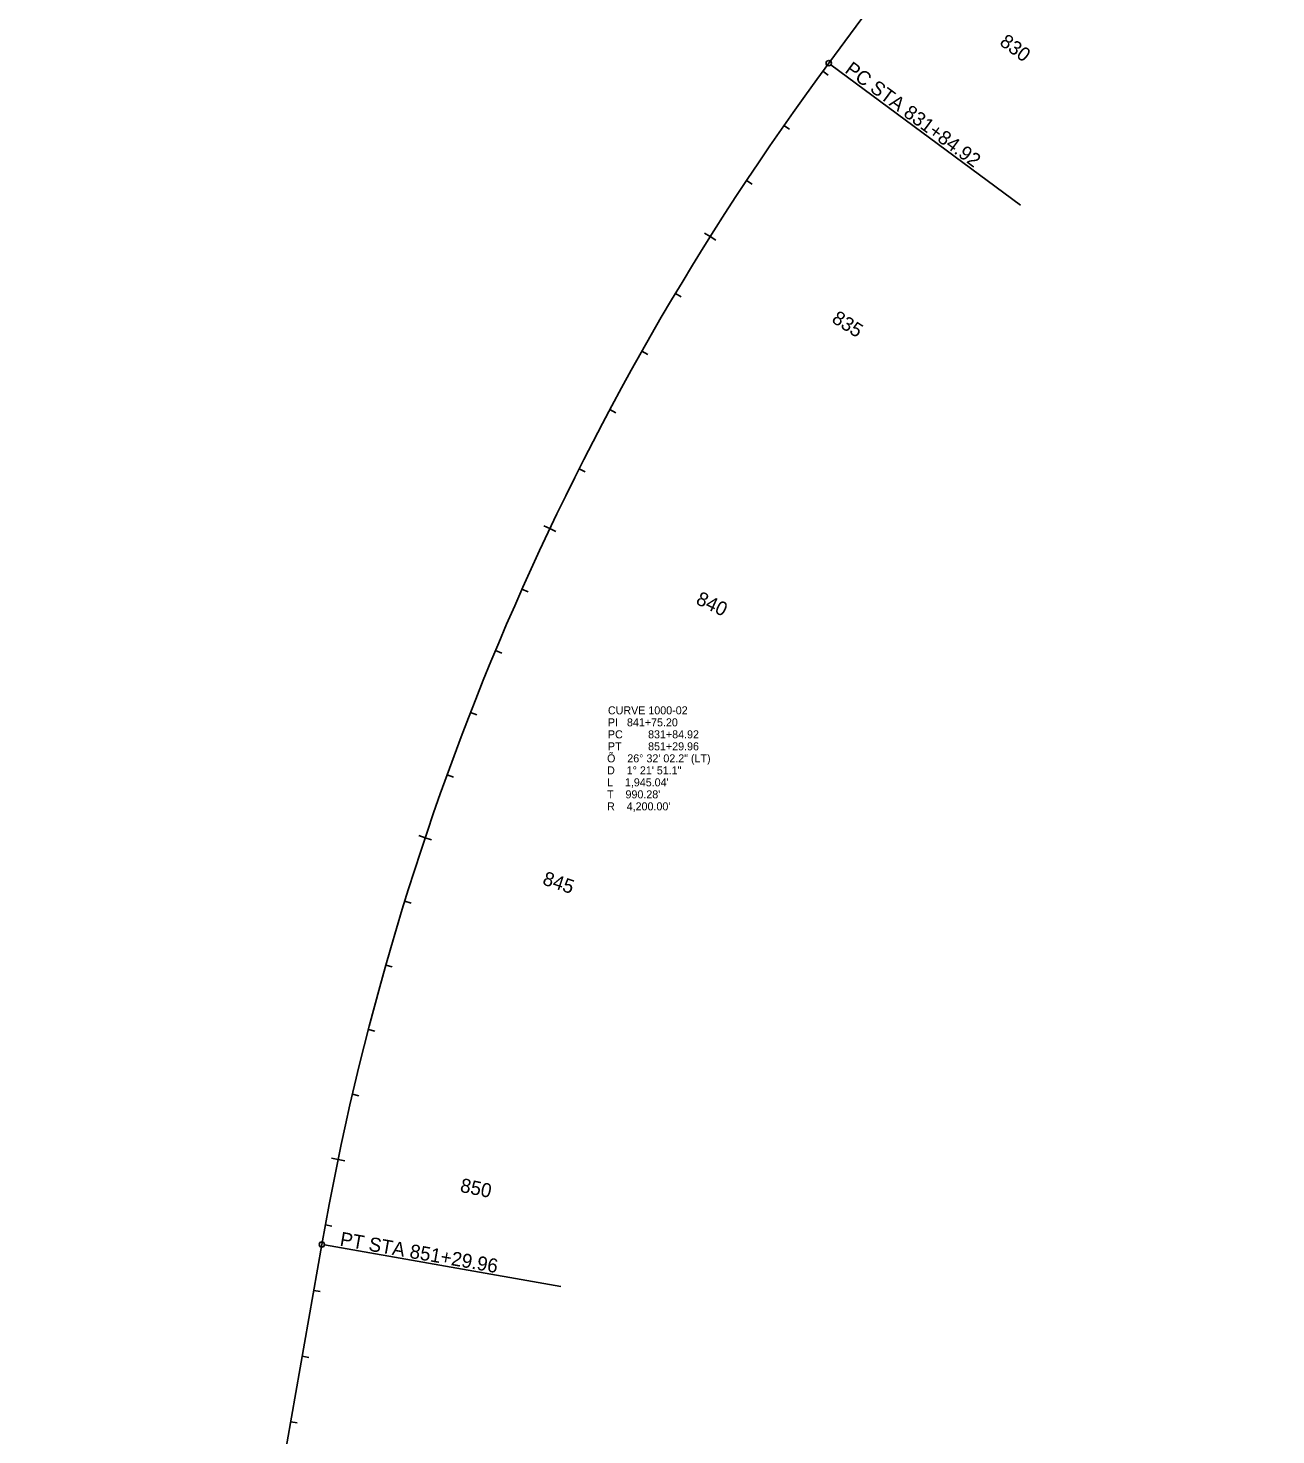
# Model space of a CAD drawing. Extents: x 2819977 to 2827606, y 113942 to 150283.
# Drawn here: x 2821007 to 2822878, y 134032 to 136141 of the extents above; entities that cross this region are included whole.
import ezdxf

# ---------------------------------------------------------------- set-up
doc = ezdxf.new("R2010")
doc.units = 0
for name, color, linetype in [('Level 63', 7, 'Continuous'), ('Roadway-Safety', 7, 'Continuous'), ('Roadway-Walls', 7, 'Continuous'), ('Utility-Power', 7, 'Continuous')]:
    doc.layers.add(name, color=color, linetype=linetype)

msp = doc.modelspace()

# ---------------------------------------------------------------- linework, layer by layer
at = {"layer": 'Level 63'}
for centre in [(2822207.8, 136088.7), (2821447.5, 134317.2)]:
    msp.add_circle(centre, 4, dxfattribs=at)
at = {"layer": 'Roadway-Safety'}
for p, q in [((2822211, 136086.3), (2822495.5, 135875.9)), ((2821451.5, 134316.6), (2821805.8, 134254.3))]:
    msp.add_line(p, q, dxfattribs=at)
at = {"layer": 'Utility-Power'}
for p, q in [((2822878.3, 136994.9), (2822207.8, 136088.7)), ((2822198.9, 136076.5), (2822206.9, 136070.6)), ((2822140.6, 135995.2), (2822148.8, 135989.5)), ((2822084.4, 135912.6), (2822092.7, 135907.1)), ((2822030.1, 135828.6), (2822021.6, 135833.9)), ((2822030.1, 135828.6), (2822038.5, 135823.3)), ((2821977.8, 135743.4), (2821986.4, 135738.2)), ((2821927.6, 135656.9), (2821936.3, 135652)), ((2821879.4, 135569.3), (2821888.3, 135564.5)), ((2821833.4, 135480.5), (2821842.3, 135476)), ((2821789.5, 135390.7), (2821780.4, 135394.9)), ((2821789.5, 135390.7), (2821798.5, 135386.4)), ((2821747.7, 135299.8), (2821756.8, 135295.7)), ((2821708.1, 135208), (2821717.3, 135204.1)), ((2821670.7, 135115.2), (2821680, 135111.6)), ((2821635.5, 135021.6), (2821644.9, 135018.2)), ((2821602.5, 134927.2), (2821593.1, 134930.4)), ((2821602.5, 134927.2), (2821612, 134924)), ((2821571.8, 134832.1), (2821581.4, 134829.1)), ((2821543.4, 134736.2), (2821553, 134733.5)), ((2821517.3, 134639.7), (2821527, 134637.2)), ((2821493.5, 134542.5), (2821503.2, 134540.3)), ((2821472, 134444.9), (2821462.2, 134446.9)), ((2821472, 134444.9), (2821481.8, 134442.8)), ((2821452.8, 134346.7), (2821462.6, 134344.9)), ((2821447.5, 134317.2), (2821007.1, 131809.7)), ((2821435.4, 134248.3), (2821445.2, 134246.5)), ((2821418.1, 134149.8), (2821427.9, 134148)), ((2821400.8, 134051.3), (2821410.6, 134049.6))]:
    msp.add_line(p, q, dxfattribs=at)
msp.add_arc((2825584.2, 133590.7), 4200, 143.5041, 170.0381, dxfattribs=at)

# ---------------------------------------------------------------- texts
at = {"layer": 'Roadway-Safety'}
for s, rotation, p in [('PC STA 831+84.92', 323.5041, (2822230.5, 136075.6)), ('PT STA 851+29.96', 350.0381, (2821473.6, 134315.7))]:
    msp.add_text(s, height=21, rotation=rotation, dxfattribs=at).set_placement(p)
at = {"layer": 'Roadway-Walls'}
for s, p in [('CURVE 1000-02', (2821876.6, 135112.2)), ('PI   841+75.20', (2821876.6, 135094.2)), ('PC', (2821876.6, 135076.2)), ('PT', (2821876.6, 135058.2)), ('831+84.92', (2821936.8, 135076.2)), ('851+29.96', (2821936.8, 135058.2)), ('Õ    26%%d 32\' 02.2" (LT)', (2821875.3, 135040.2)), ('D    1%%d 21\' 51.1"', (2821875.3, 135022.2)), ("L    1,945.04'", (2821875.3, 135004.2)), ("T    990.28'", (2821875.3, 134986.2)), ("R    4,200.00'", (2821875.3, 134968.2))]:
    msp.add_text(s, height=12, dxfattribs=at).set_placement(p)
at = {"layer": 'Utility-Power'}
for s, rotation, p in [(' 830', 323.5041, (2822456.3, 136121.8)), (' 835', 327.8024, (2822204.2, 135705.3)), (' 840', 334.6233, (2822000, 135281.8)), (' 845', 341.4442, (2821769.8, 134860)), (' 850', 348.2651, (2821646.1, 134398))]:
    msp.add_text(s, height=21, rotation=rotation, dxfattribs=at).set_placement(p)

doc.saveas('drawing.dxf')
